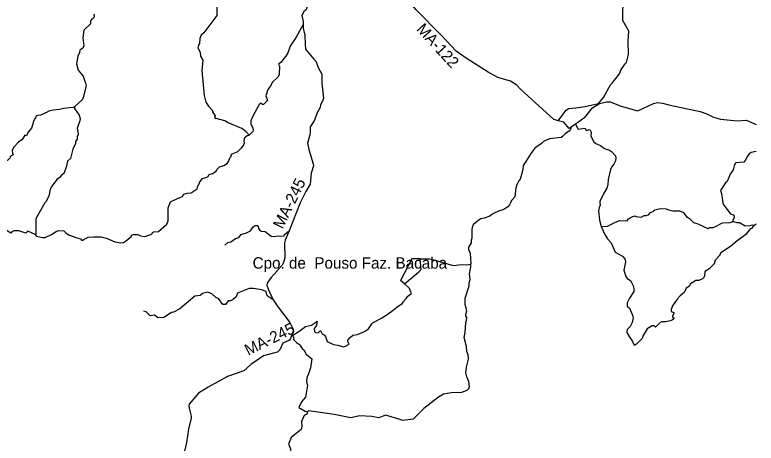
# Model space of a CAD drawing. Extents: x 332 to 501, y 9447 to 9559.
# Drawn here: x 475.23 to 500, y 9479.97 to 9494.28 of the extents above; entities that cross this region are included whole.
import ezdxf

# ---------------------------------------------------------------- set-up
doc = ezdxf.new("R2010")
doc.units = 0
for name, color, linetype in [('Level 1', 7, 'Continuous'), ('Level 13', 7, 'Continuous'), ('Level 2', 7, 'Continuous'), ('Level 31', 7, 'Continuous'), ('Level 4', 7, 'Continuous'), ('Level 5', 7, 'Continuous'), ('Level 6', 7, 'Continuous')]:
    doc.layers.add(name, color=color, linetype=linetype)

msp = doc.modelspace()

# ---------------------------------------------------------------- linework, layer by layer
at = {"layer": 'Level 1'}
msp.add_lwpolyline([(488.4941, 9486.1263), (488.1224, 9485.4087)], dxfattribs=at)
at = {"layer": 'Level 2'}
for points in [[(485.2694, 9494.7905), (485.0123, 9494.6047), (484.9653, 9494.448), (484.9026, 9494.4009), (484.8242, 9494.2599), (484.8712, 9494.0561), (484.8712, 9493.9592)], [(489.4927, 9493.5897), (488.6259, 9494.4616), (488.4494, 9494.6812)], [(484.8712, 9493.9592), (484.8712, 9493.8366), (484.9182, 9493.6015), (484.9357, 9493.2839)], [(490.7077, 9492.5743), (490.3148, 9492.8266), (489.9731, 9493.0696), (489.4927, 9493.5897)], [(484.9357, 9493.2839), (484.9496, 9493.1313), (485.2269, 9492.7943)], [(491.3698, 9492.188), (491.0433, 9492.3587), (490.7077, 9492.5743)], [(491.8775, 9492.0072), (491.7897, 9492.0618), (491.3698, 9492.188)], [(492, 9491.9312), (491.8892, 9492)], [(492.1294, 9491.7947), (492, 9491.9312)], [(493.286, 9490.7709), (493.2376, 9490.784), (492.1294, 9491.7947)], [(494.7665, 9491.3201), (495.0154, 9491.3736), (495.1249, 9491.3736), (495.4846, 9491.2251), (496, 9491.0819)], [(496, 9491.0819), (496.0476, 9491.0687), (496.5753, 9491.3134), (496.7004, 9491.3525), (496.8725, 9491.329), (497.1305, 9491.2586), (498.1314, 9491.0473), (498.3504, 9490.9769), (498.5693, 9490.8596), (498.8117, 9490.797), (499.3669, 9490.7344), (499.664, 9490.7579), (500, 9490.6152)], [(493.3891, 9490.743), (493.6548, 9491.0999), (493.7252, 9491.1469), (493.9795, 9491.1739)], [(493.9795, 9491.1739), (494.2882, 9491.2172), (494.7379, 9491.3139)], [(494.2682, 9490.8426), (494.5279, 9491.1763), (494.7665, 9491.3201)], [(494.7379, 9491.3139), (494.7665, 9491.3201)], [(493.3891, 9490.743), (493.286, 9490.7709)], [(493.7502, 9490.4781), (493.5703, 9490.694), (493.3891, 9490.743)], [(493.9633, 9490.6274), (493.8155, 9490.5238)], [(494.0339, 9490.6769), (493.9633, 9490.6274)], [(494.1943, 9490.7892), (494.0339, 9490.6769)], [(494.2656, 9490.8392), (494.1943, 9490.7892)], [(494.2656, 9490.8392), (494.2682, 9490.8426)], [(493.8155, 9490.5238), (493.7502, 9490.4781)]]:
    msp.add_lwpolyline(points, dxfattribs=at)
at = {"layer": 'Level 4'}
for points in [[(495.543, 9494.1488), (495.5533, 9494.8413), (495.7181, 9495.2394), (495.687, 9495.3514), (495.5627, 9495.5861), (495.563, 9495.6858)], [(495.6221, 9492.6427), (495.6653, 9492.6891), (495.7305, 9492.9566), (495.7274, 9493.3983), (495.743, 9493.7322), (495.5409, 9494.0868), (495.543, 9494.1488)], [(485.2269, 9492.7943), (485.286, 9492.735), (485.3841, 9492.5004), (485.4926, 9492.2974), (485.4959, 9492)], [(495.1854, 9492), (495.4321, 9492.3127), (495.4912, 9492.4527), (495.6221, 9492.6427)], [(485.4959, 9492), (485.5451, 9491.5006), (485.5171, 9491.392), (485.4506, 9491.2694), (485.431, 9491.1835), (485.3456, 9491.0292), (485.237, 9490.742), (485.097, 9490.5353), (485.104, 9490.3566), (485.09, 9490.2655), (485.0094, 9489.9974), (485.0515, 9489.7767), (485.2055, 9489.3049), (485.209, 9489.2313), (485.132, 9488.9896), (485.1005, 9488.6195), (484.9569, 9488.3742), (484.7678, 9488)], [(494.7379, 9491.3139), (494.8953, 9491.5123), (495.1377, 9491.9415), (495.1854, 9492)], [(484.7678, 9488), (484.3986, 9487.0688)], [(484.3986, 9487.0688), (484.2637, 9486.7562), (484.2462, 9486.6686), (484.2532, 9486.1676), (484.2147, 9486.0042), (484.1622, 9485.9131), (484, 9485.7288)], [(484, 9485.7288), (483.7945, 9485.5032), (483.7035, 9485.3876), (483.665, 9485.3121), (483.658, 9485.249), (483.707, 9485.0984), (483.8681, 9484.7586)], [(483.8681, 9484.7586), (484, 9484.5566)], [(484, 9484.5566), (484.4196, 9484)], [(484.4196, 9484), (484.5333, 9483.7797), (484.5298, 9483.7131), (484.4423, 9483.4644), (484.4072, 9483.4099), (484.1832, 9483.3118), (484.0921, 9483.0911), (484.0221, 9483.021)], [(484, 9483.0153), (483.546, 9482.8887), (483.1165, 9482.6014), (482.889, 9482.3885), (482.3428, 9482.1993), (481.6893, 9481.8455), (481.3673, 9481.6458)], [(484.0221, 9483.021), (484, 9483.0153)], [(481.3673, 9481.6458), (481.0568, 9481.2806), (481.0463, 9481.2245), (481.0568, 9481.1475), (481.1303, 9480.8812), (481.1303, 9480.8147), (481.0393, 9480.4398), (480.9663, 9480)], [(480.9663, 9480), (480.906, 9479.7106), (480.899, 9479.5635), (480.9515, 9479.3603), (480.9865, 9479.2832), (481.0005, 9479.1921), (480.969, 9479.115), (480.8745, 9478.9819), (480.7449, 9478.6806), (480.7379, 9478.6226), (480.7904, 9478.4194), (480.7729, 9478.2477), (480.7344, 9478.1776), (480.611, 9478.0848)]]:
    msp.add_lwpolyline(points, dxfattribs=at)
at = {"layer": 'Level 5'}
for points in [[(482.1514, 9495.1518), (482.1514, 9494.9312), (482.1232, 9494.816), (482.0577, 9494.6579), (481.9877, 9494.5585), (481.9837, 9494.2513), (481.5459, 9493.676), (481.4595, 9493.5958), (481.4194, 9493.4842), (481.4041, 9493.3245), (481.3651, 9493.2636), (481.345, 9493.1773), (481.4232, 9493.0348), (481.4418, 9492.8958), (481.5097, 9492.7647), (481.4808, 9492.4204), (481.5601, 9491.5793), (481.6136, 9491.3652), (481.7029, 9491.2251), (481.8417, 9491.0797), (481.8354, 9491.0358), (481.9326, 9490.9062), (481.9023, 9490.8503), (481.9598, 9490.8192)], [(484.8712, 9493.9592), (484.6336, 9493.529), (484.4331, 9493.2286), (484.3544, 9493.0125), (484.2914, 9492.8949), (484.2182, 9492.8236), (484.127, 9492.6995), (484.0418, 9492.6291)], [(484.0418, 9492.6291), (484.0766, 9492.5599), (484.0684, 9492.2828), (484.0332, 9492.2104), (483.8342, 9492.0167), (483.783, 9491.9189), (483.6817, 9491.7879), (483.6169, 9491.5743), (483.6742, 9491.4131), (483.5453, 9491.2841), (483.5066, 9491.2798), (483.4622, 9491.3228), (483.4006, 9491.2855), (483.1688, 9490.876), (483.121, 9490.7362), (483.1235, 9490.6233), (483.1853, 9490.5024), (483.1955, 9490.43), (483.1836, 9490.3837), (483.0577, 9490.2562)], [(491.8892, 9492), (491.8775, 9492.0072)], [(477.2257, 9491.2059), (477.2268, 9491.1531), (477.3835, 9490.9259), (477.4151, 9490.816), (477.4031, 9490.737), (477.3129, 9490.4989), (477.344, 9490.3773), (477.3483, 9490.2792), (477.3126, 9490.2011), (477.3131, 9490.1221), (477.2619, 9490.0455), (477.266, 9489.9865), (477.1693, 9489.7928), (477.0938, 9489.4848), (476.9916, 9489.3861), (476.9488, 9489.1908), (476.8942, 9489.038)], [(483.0577, 9490.2562), (482.9623, 9490.3687), (482.8173, 9490.4809), (482.3354, 9490.6783), (482.2464, 9490.7363), (481.9598, 9490.8192)], [(493.9633, 9490.6274), (494.0562, 9490.4628), (494.2828, 9490.4925)], [(493.8155, 9490.5238), (493.7909, 9490.4319), (493.7692, 9490.408), (493.6191, 9490.3057), (493.5439, 9490.2249)], [(494.2828, 9490.4925), (494.3251, 9490.42), (494.4432, 9490.4446)], [(494.4432, 9490.4446), (494.485, 9490.3619), (494.48, 9490.225), (494.577, 9490.039), (494.639, 9489.976), (494.796, 9489.912), (494.935, 9489.81), (495.101, 9489.764), (495.167, 9489.715), (495.301, 9489.571), (495.313, 9489.503), (495.305, 9489.408), (495.241, 9489.2902)], [(482.8075, 9489.8367), (482.8757, 9489.9141), (482.9118, 9489.9959), (482.8991, 9490.0628), (482.9224, 9490.1786), (482.9978, 9490.2455), (483.0577, 9490.2562)], [(493.5285, 9490.214), (493.4832, 9490.1783), (493.0975, 9490.1406), (492.9634, 9490.0861), (492.8837, 9490.0357), (492.8334, 9489.9812), (492.6113, 9489.826), (492.4729, 9489.6498), (492.3053, 9489.3756)], [(493.5439, 9490.2249), (493.5285, 9490.214)], [(479.5746, 9486.8789), (479.7835, 9486.9419), (479.817, 9486.962), (479.8303, 9487.0088), (479.8704, 9487.0288), (480.0375, 9487.0389), (480.3115, 9487.2929), (480.3583, 9487.3966), (480.3516, 9487.8278), (480.4318, 9488.0336), (480.6891, 9488.1573), (480.8361, 9488.2074), (480.8795, 9488.2877), (480.9931, 9488.3244), (481.1268, 9488.3311), (481.3306, 9488.4715), (481.3506, 9488.5618), (481.3974, 9488.632), (481.4175, 9488.7022), (481.5043, 9488.8081), (481.6848, 9488.8682), (481.7249, 9488.9485), (481.8385, 9488.9819), (481.9554, 9489.0555), (481.9788, 9489.1089), (482.0743, 9489.2037), (482.2213, 9489.2438), (482.3249, 9489.3174), (482.375, 9489.3775), (482.4185, 9489.5046), (482.4619, 9489.5514), (482.4719, 9489.6249), (482.6824, 9489.7185), (482.8075, 9489.8367)], [(500, 9489.7142), (499.8331, 9489.6771), (499.7699, 9489.635), (499.7068, 9489.5612), (499.6331, 9489.4138), (499.591, 9489.3611), (499.3173, 9489.3401), (499.2752, 9489.2769), (499.2331, 9489.0978), (499.1278, 9488.9609), (499.0331, 9488.7081), (498.9804, 9488.666), (498.812, 9488.4132), (498.8436, 9488.3078), (498.8866, 9488)], [(492.3053, 9489.3756), (492.2117, 9489.2416), (492.2045, 9489.118), (492.1255, 9488.829), (492.0892, 9488.7434), (492.0679, 9488.7307), (492, 9488.6059)], [(495.241, 9489.2902), (495.166, 9489.187), (495.133, 9489.108), (495.051, 9488.784), (495.05, 9488.597), (495.012, 9488.494), (494.908, 9488.324), (494.778, 9488.04), (494.7764, 9488)], [(476.8942, 9489.038), (476.8677, 9488.9801), (476.7844, 9488.9124), (476.7362, 9488.8432), (476.6444, 9488.7878), (476.4736, 9488.5525), (476.4156, 9488.4592), (476.3687, 9488.2213), (476.2694, 9488.0293), (476.2399, 9488)], [(492, 9488.6059), (491.9676, 9488.4958), (491.9399, 9488.2016), (491.8267, 9488.0777), (491.7913, 9488)], [(476.2399, 9488), (475.9999, 9487.5847)], [(491.7562, 9487.9341), (491.7051, 9487.8627), (491.5664, 9487.7773), (491.3892, 9487.7175), (491.2505, 9487.6513), (491.1681, 9487.6092), (491.102, 9487.5516), (490.912, 9487.4833), (490.7989, 9487.4683), (490.7093, 9487.4149), (490.5471, 9487.2606), (490.5108, 9487.1709), (490.5045, 9487.1039)], [(491.7913, 9488), (491.7562, 9487.9341)], [(494.7764, 9488), (494.7889, 9487.926), (494.7541, 9487.846)], [(498.8866, 9488), (498.9173, 9487.9181), (499.1383, 9487.6337), (499.2331, 9487.6021), (499.2646, 9487.56), (499.2646, 9487.5074), (499.2232, 9487.415)], [(494.7541, 9487.846), (494.733, 9487.729), (494.762, 9487.42), (494.824, 9487.208)], [(494.824, 9487.208), (495.0378, 9487.2173), (495.3045, 9487.3594), (495.44, 9487.4076), (495.6958, 9487.4032), (495.7374, 9487.4644), (495.8795, 9487.5475), (495.9516, 9487.5628), (495.98, 9487.541), (496.1593, 9487.5235), (496.2555, 9487.5738), (496.3276, 9487.576), (496.402, 9487.6), (496.4676, 9487.6722), (496.5697, 9487.7179)], [(499.2232, 9487.415), (499.212, 9487.3704), (499.1173, 9487.3283), (498.8646, 9487.3178), (498.5594, 9487.1703), (498.433, 9487.1598), (498.3909, 9487.1282), (498.0646, 9487.2862), (497.9172, 9487.3283), (497.8014, 9487.4442), (497.7067, 9487.5074), (497.5804, 9487.6653), (497.454, 9487.718), (497.2119, 9487.718), (497.0856, 9487.7496), (497.0014, 9487.7917), (496.7909, 9487.8023), (496.6119, 9487.7496), (496.5697, 9487.7179)], [(475.9999, 9487.5847), (475.9375, 9487.4614), (475.9341, 9487.1844)], [(499.921, 9487.247), (499.8647, 9487.2546), (499.791, 9487.2335), (499.6331, 9487.223), (499.4436, 9487.3283), (499.3699, 9487.3283), (499.2541, 9487.3704), (499.2232, 9487.415)], [(475.9341, 9487.1844), (475.9404, 9486.9617), (475.919, 9486.9466)], [(494.824, 9487.208), (494.957, 9486.919), (495.0351, 9486.7978)], [(499.142, 9486.552), (499.362, 9486.742), (499.683, 9486.976), (499.818, 9487.148), (499.867, 9487.149), (499.921, 9487.247)], [(475.919, 9486.9466), (475.9591, 9486.8921), (475.9999, 9486.8784)], [(475.9999, 9486.8784), (476.1613, 9486.8457), (476.2507, 9486.8454), (476.4547, 9486.9398), (476.6112, 9487.0407), (476.6988, 9487.0728), (476.8663, 9487.0654), (476.9516, 9486.9886), (477.0611, 9486.9208), (477.2781, 9486.8384)], [(477.4291, 9486.7942), (477.4604, 9486.7572), (477.5047, 9486.7572), (477.5458, 9486.792), (477.6818, 9486.8489), (477.8589, 9486.8679), (478.1183, 9486.8616), (478.2986, 9486.8173), (478.5737, 9486.6939), (478.7762, 9486.6623), (478.8647, 9486.6749), (478.9659, 9486.7445), (479.1272, 9486.89), (479.1367, 9486.9153), (479.2, 9486.9375), (479.3423, 9486.9438), (479.4309, 9486.8995), (479.5746, 9486.8789)], [(490.5049, 9487.0928), (490.5044, 9486.8186), (490.483, 9486.7588), (490.483, 9486.6698), (490.3917, 9486.5182), (490.3853, 9486.4819), (490.3853, 9486.437), (490.4451, 9486.3238), (490.473, 9485.96)], [(490.5045, 9487.1039), (490.5049, 9487.0928)], [(477.2781, 9486.8384), (477.4291, 9486.7942)], [(495.0351, 9486.7978), (495.153, 9486.662), (495.291, 9486.356), (495.5359, 9486.222), (495.614, 9486.128), (495.631, 9486.028), (495.582, 9485.749), (495.645, 9485.539), (495.6863, 9485.4749)], [(497.865, 9485.34), (497.986, 9485.415), (498.095, 9485.422), (498.213, 9485.469), (498.263, 9485.52), (498.285, 9485.568), (498.301, 9485.694), (498.335, 9485.741), (498.461, 9485.833), (498.604, 9485.979), (498.644, 9486.102), (498.797, 9486.268), (498.82, 9486.339), (499.142, 9486.552)], [(488.2537, 9485.2897), (488.7358, 9485.6934), (488.8099, 9485.7755), (488.7797, 9486.1264)], [(488.7797, 9486.1264), (488.4941, 9486.1263)], [(488.7797, 9486.1264), (489.0863, 9486.1315), (489.2282, 9486.1006)], [(489.2282, 9486.1006), (489.882, 9485.9058), (490.1664, 9485.9364), (490.3355, 9485.9285), (490.47, 9485.952)], [(488.2537, 9485.2897), (488.1224, 9485.4087)], [(495.6863, 9485.4749), (495.806, 9485.401), (495.898, 9485.202), (495.912, 9485.122), (495.911, 9485.039), (495.765, 9484.8159)], [(488.442, 9485.077), (488.422, 9485.142), (488.2537, 9485.2897)], [(497.865, 9485.34), (497.7986, 9485.2839), (497.7694, 9485.217), (497.6565, 9485.1501), (497.6021, 9485.0121), (497.4558, 9484.8908), (497.3555, 9484.782), (497.2092, 9484.5562), (497.1632, 9484.4349), (497.1549, 9484.368), (497.2301, 9484.3512), (497.2552, 9484.3303), (497.205, 9484.2299), (497.2092, 9484.1839), (497.251, 9484.1547), (497.2468, 9484.1296), (497.205, 9484.0877), (497.1381, 9484.0543), (496.9751, 9484.025), (496.8497, 9484.025), (496.7939, 9484)], [(483.8681, 9484.7586), (483.6591, 9484.8949), (483.63, 9485.037), (483.4699, 9485.094), (483.2037, 9485.1441), (483.0595, 9485.1341), (482.6786, 9484.9831), (482.6256, 9484.8579), (482.5427, 9484.7828), (482.4406, 9484.7277), (482.3616, 9484.7271), (482.2737, 9484.6009), (482.1797, 9484.609), (482.0415, 9484.8042), (481.9477, 9484.8333), (481.8129, 9484.9664), (481.6848, 9485.0173), (481.4996, 9484.9693), (481.4206, 9484.9012), (481.2457, 9484.8822), (480.7428, 9484.4648), (480.5406, 9484.3509), (480.4726, 9484.3399), (480.2086, 9484.175), (480.0138, 9484.156), (480, 9484.1675)], [(488.355, 9484.874), (488.475, 9484.971), (488.4827, 9484.9986)], [(488.4827, 9484.9986), (488.442, 9485.077)], [(488, 9484.5147), (488.172, 9484.64), (488.227, 9484.702)], [(488.227, 9484.702), (488.243, 9484.74)], [(488.243, 9484.74), (488.322, 9484.821)], [(488.322, 9484.821), (488.355, 9484.874)], [(495.694, 9484.666), (495.688, 9484.554), (495.771, 9484.486), (495.873, 9484.251), (495.8861, 9484.15)], [(495.765, 9484.8159), (495.694, 9484.666)], [(487.832, 9484.385), (488, 9484.5147)], [(480, 9484.1675), (479.8997, 9484.2511), (479.7536, 9484.2221), (479.6178, 9484.3593), (479.5497, 9484.3773)], [(487.2105, 9484), (487.501, 9484.159), (487.7543, 9484.332)], [(487.7543, 9484.332), (487.832, 9484.385)], [(484.5219, 9483.5855), (484.724, 9483.704), (484.949, 9483.867), (485.149, 9483.912), (485.2741, 9484)], [(485.3257, 9484), (485.307, 9483.908), (485.236, 9483.801), (485.249, 9483.703), (485.282, 9483.669), (485.3641, 9483.6559), (485.4458, 9483.7388)], [(485.2741, 9484), (485.3362, 9484.0519), (485.3257, 9484)], [(486.4392, 9483.5062), (486.5211, 9483.581), (486.685, 9483.608), (486.916, 9483.705), (487.054, 9483.796), (487.163, 9483.958), (487.2105, 9484)], [(495.8603, 9484), (495.796, 9483.873), (495.693, 9483.77), (495.681, 9483.674), (495.758, 9483.531), (495.873, 9483.37), (495.917, 9483.2733), (495.912, 9483.247)], [(495.8861, 9484.15), (495.8603, 9484)], [(496.7939, 9484), (496.6365, 9483.8451), (496.5835, 9483.8971), (496.5208, 9483.893), (496.3619, 9483.7884), (496.2198, 9483.5667), (496.1864, 9483.4663), (496, 9483.2771)], [(485.4458, 9483.7388), (485.503, 9483.625), (485.572, 9483.587), (485.615, 9483.536), (485.664, 9483.374), (485.8799, 9483.266), (486.029, 9483.25), (486.218, 9483.191), (486.277, 9483.211), (486.408, 9483.276), (486.359, 9483.3671), (486.364, 9483.411), (486.4392, 9483.5062)], [(484.5219, 9483.5855), (484.5118, 9483.5667), (484.5534, 9483.494), (484.543, 9483.4418), (484.6426, 9483.331), (484.779, 9483.2473), (484.779, 9483.2168), (484.8351, 9483.1382), (484.8926, 9483.0902), (484.968, 9482.9462), (485.1567, 9482.793), (485.1108, 9482.4903), (485.0478, 9482.2892)], [(485.0478, 9482.2892), (485.0045, 9482.192), (484.9735, 9482.0676), (484.9842, 9481.9707), (485.0118, 9481.9064), (484.9447, 9481.5104), (484.8126, 9481.3501), (484.7214, 9481.1673), (484.9329, 9481.0448), (485.011, 9481.0234)], [(485, 9480.9788), (484.9886, 9480.9445), (484.902, 9480.8965), (484.8075, 9480.6964), (484.8272, 9480.5443), (484.8019, 9480.4339), (484.4627, 9480.1633), (484.3978, 9480)], [(485.011, 9481.0234), (485, 9480.9788)], [(484.3978, 9480), (484.3774, 9479.9387), (484.4483, 9479.7814), (484.4575, 9479.6482)]]:
    msp.add_lwpolyline(points, dxfattribs=at)
at = {"layer": 'Level 6'}
for points in [[(477.862, 9494.3058), (477.8899, 9494.2686), (477.8899, 9494.2245), (477.8574, 9494.1665), (477.7947, 9494.1247), (477.7669, 9494.076), (477.7646, 9493.9762), (477.5418, 9493.7704), (477.5093, 9493.5058), (477.5418, 9493.2422), (477.5047, 9493.1633), (477.4026, 9493.0983), (477.391, 9493.0217), (477.3423, 9492.901), (477.2931, 9492.6364), (477.3554, 9492.4262), (477.5188, 9492.2316), (477.601, 9492)], [(477.601, 9492), (477.6122, 9491.9046), (477.5188, 9491.523), (477.4799, 9491.4374), (477.2257, 9491.2059)], [(477.2257, 9491.2059), (477.1842, 9491.1827), (476.8651, 9491.1516), (476.725, 9491.1127), (476.5148, 9491.0971), (476.367, 9491.0659), (476.2736, 9491.0036), (476.0868, 9490.9258), (475.9999, 9490.9149)], [(475.9999, 9490.9149), (475.9622, 9490.9102), (475.9, 9490.809), (475.8455, 9490.7), (475.8377, 9490.6221), (475.791, 9490.4898), (475.6743, 9490.3496), (475.6276, 9490.2406), (475.5731, 9490.2562), (475.4797, 9490.1161), (475.3552, 9490.0226), (475.1917, 9489.8513), (475.145, 9489.7501), (475.1528, 9489.6597), (475.1839, 9489.6052), (475.0828, 9489.5507), (475.0672, 9489.4884), (475.0049, 9489.4261), (474.9271, 9489.3794), (474.8571, 9489.3016)], [(475.919, 9486.9466), (475.6686, 9487.0504), (475.5991, 9486.9846), (475.3651, 9487.0614), (475.2005, 9487.0651), (475.1384, 9487.0321), (475.0981, 9486.9882), (474.8458, 9487.1492), (474.7873, 9487.2663), (474.6557, 9487.4017), (474.185, 9487.5653), (474.0533, 9487.6495), (473.8815, 9487.8141), (473.7462, 9487.8617), (473.5889, 9487.8434), (473.5377, 9487.8214), (473.4902, 9487.8251), (473.3412, 9487.8983), (473.2016, 9488)], [(482.2551, 9486.5874), (482.3517, 9486.6739), (482.4483, 9486.6942), (482.6109, 9486.806), (482.7126, 9486.8416), (482.7939, 9486.9382), (482.9718, 9486.9941), (483.104, 9487.0653), (483.1955, 9487.2025), (483.2667, 9487.2381), (483.3379, 9487.2381), (483.3582, 9487.2229), (483.3734, 9487.1466), (483.4192, 9487.0805), (483.4649, 9487.05), (483.5971, 9487.045), (483.8005, 9486.8823), (483.897, 9486.8772), (484, 9486.8975)], [(499.921, 9487.247), (500, 9487.3)], [(484, 9486.8975), (484.0902, 9486.8874), (484.2326, 9486.8975), (484.2427, 9486.9433), (484.3986, 9487.0688)], [(490.2954, 9484), (490.323, 9484.063), (490.337, 9484.172), (490.304, 9484.232), (490.301, 9484.282), (490.331, 9484.396), (490.278, 9484.605), (490.281, 9484.82), (490.411, 9485.223), (490.413, 9485.324), (490.443, 9485.44), (490.421, 9485.634), (490.468, 9485.859), (490.47, 9485.952)], [(490.47, 9485.952), (490.473, 9485.96)], [(490.08, 9481.67), (490.1628, 9481.6729), (490.342, 9481.742), (490.406, 9481.795), (490.425, 9481.865), (490.402, 9482.036), (490.337, 9482.195), (490.305, 9482.32), (490.321, 9482.515), (490.386, 9482.781), (490.381, 9482.922), (490.335, 9483.035), (490.322, 9483.206), (490.25, 9483.507), (490.277, 9483.665), (490.2954, 9484)], [(496, 9483.2771), (495.9481, 9483.2447), (495.912, 9483.247)], [(490.08, 9481.67), (489.818, 9481.6593), (489.5601, 9481.6134), (489.3853, 9481.5074), (488.8953, 9481.1287), (488.5386, 9480.777), (488.1959, 9480.7275), (488, 9480.7965)], [(485.048, 9481.0533), (485.011, 9481.0234)], [(488, 9480.7965), (487.6209, 9480.906), (487.3913, 9480.8229), (487.1643, 9480.8695), (486.7457, 9480.8907), (486.4578, 9480.8218), (485.9022, 9480.9367), (485.048, 9481.0533)]]:
    msp.add_lwpolyline(points, dxfattribs=at)

# ---------------------------------------------------------------- texts
at = {"layer": 'Level 13'}
msp.add_text('Cpo. de  Pouso Faz. Bacaba', height=0.38, dxfattribs=at).set_placement((483.178, 9485.803))
at = {"layer": 'Level 31'}
for s, rotation, p in [('MA-122', 312.48978, (488.6242, 9493.7794)), ('MA-245', 63.82223, (484.1782, 9487.1032)), ('MA-245', 26.20596, (483.0293, 9482.8896))]:
    msp.add_text(s, height=0.38, rotation=rotation, dxfattribs=at).set_placement(p)

doc.saveas('drawing.dxf')
